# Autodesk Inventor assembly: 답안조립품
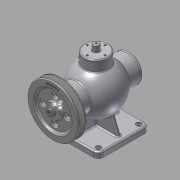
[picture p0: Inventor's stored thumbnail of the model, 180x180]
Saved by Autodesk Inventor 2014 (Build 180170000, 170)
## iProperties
Created: 2015-10
Part Number: 답안조립품
Document SubType Name: Assembly
Designer: youjin03
Author: youjin03
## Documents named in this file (16)
- C:\Users\youjin03\Desktop\451010V1015\답안조립품.iam
- C:\Users\youjin03\Desktop\451010V1015\본체.ipt
- C:\Users\youjin03\Desktop\451010V1015\뒤커버.ipt
- C:\Users\youjin03\Desktop\451010V1015\앞커버.ipt
- C:\Users\youjin03\Desktop\451010V1015\상부커버.ipt
- C:\Users\youjin03\Desktop\451010V1015\볼트 M4 x 16.ipt
- C:\Users\youjin03\Desktop\451010V1015\볼트 M 4 x 12.ipt
- C:\Users\youjin03\Desktop\451010V1015\오일실 15 30 7.ipt
- C:\Users\youjin03\Desktop\451010V1015\편심축.ipt
- C:\Users\youjin03\Desktop\451010V1015\베어링- 6202.ipt
- KS B 2023 - 6202 - 15 x 35 x 11 - 7.8.ipt
- C:\Users\youjin03\Desktop\451010V1015\부시.ipt
- C:\Users\youjin03\Desktop\451010V1015\키 4 x 4 x 12.ipt
- C:\Users\youjin03\Desktop\451010V1015\V-벨트풀리.ipt
- C:\Users\youjin03\Desktop\451010V1015\너트 M8.ipt
- C:\Users\youjin03\Desktop\451010V1015\슬라이드.ipt
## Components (15 placed, 4 different names)
1. KS B 2023 - 6202 - 15 x 35 x 11 - 7.8:1
2. KS B 2023 - 6202 - 15 x 35 x 11 - 7.8:2
3. V-벨트풀리:1
4. ISO 4762 M4 x 16:1
5. ISO 4762 M4 x 16:3
6. ISO 4762 M4 x 16:4
7. ISO 4762 M4 x 16:5
8. ISO 4762 M4 x 16:2
9. ISO 4762 M4 x 16:6
10. ISO 4762 M4 x 16:7
11. ISO 4762 M4 x 16:8
12. KS B 1021 - 에 따름 ISO 1207 - 미터 A  M 4 x 12:1
13. KS B 1021 - 에 따름 ISO 1207 - 미터 A  M 4 x 12:2
14. KS B 1021 - 에 따름 ISO 1207 - 미터 A  M 4 x 12:3
15. KS B 1021 - 에 따름 ISO 1207 - 미터 A  M 4 x 12:4
